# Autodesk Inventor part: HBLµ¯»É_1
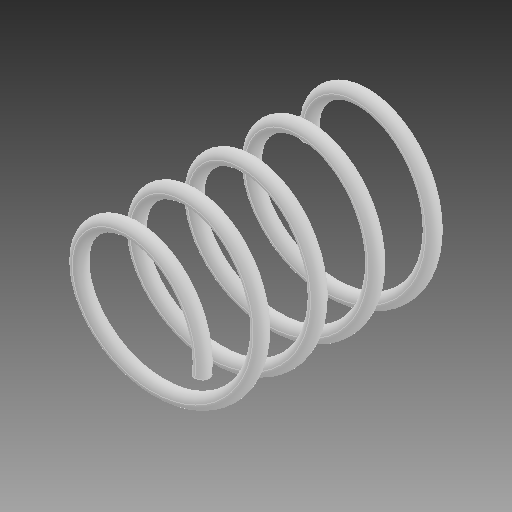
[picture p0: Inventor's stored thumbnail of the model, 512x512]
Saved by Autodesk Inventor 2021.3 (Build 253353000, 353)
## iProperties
Created: 2020-03
Part Number: HBLµ¯»É_1
Material: Ogólny
Document SubType Name: Modeling
Designer: Przemyslaw Krecisz
Density: 1 g/cm^3
Appearance: Domyślna
Author: Przemyslaw Krecisz
Revision Number: ÈÎºÎ
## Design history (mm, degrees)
feature "É¨Ãè1"
node "Bryła1"
